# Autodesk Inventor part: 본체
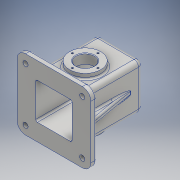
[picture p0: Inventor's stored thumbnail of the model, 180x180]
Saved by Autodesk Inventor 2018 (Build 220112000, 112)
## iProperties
Created: 2022-11
Part Number: 본체
Material: 알루미늄 6061
Document SubType Name: Modeling
Designer: home
Density: 2.7 g/cm^3
Appearance: 알루미늄 - 평지
Mass: 1129.89 g
Surface Area: 1015.9 cm^2
Volume: 418.477 cm^3
Author: home
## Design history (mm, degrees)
sketch "스케치1"
  geometry: L1 (-50, 62)-(50, 62); L2 (65, 47)-(65, -47); L3 (50, -62)-(-50, -62); L4 (-65, -47)-(-65, 47); L5 (-65, 62)-(65, -62); L6 (65, 62)-(-65, -62); A1 r 15 centre (50, 47) between (65, 47) and (50, 62); A2 r 15 centre (50, -47) between (50, -62) and (65, -47); A3 r 15 centre (-50, 47) between (-50, 62) and (-65, 47); A4 r 15 centre (-50, -47) between (-65, -47) and (-50, -62); 1 further point
  constraints: 12 end point, 8 point on circle, 8 point on line, 8 tangent, 4 centre point, 3 equal radius, 2 midpoint, 2 parallel, 1 horizontal, 1 perpendicular
  dimensions: "d2" = 15 radius of A1; "d3" = 46.3532 deg angle of L5 L2; "d4" = 130 distance between parallel lines of L2 L4
extrude "돌출1" new body sketch "스케치1" distance "d5" = 10; taper "d6" = 0 deg
sketch "스케치2"
  geometry: L1 (40, -40)-(-40, -40); L2 (-40, -40)-(-40, 40); L3 (-40, 40)-(40, 40); L4 (40, 40)-(40, -40); L5 (40, -40)-(-40, 40); L6 (-40, -40)-(40, 40); 1 further point
  constraints: 12 end point, 2 midpoint, 2 parallel, 1 horizontal, 1 perpendicular
  dimensions: "d7" = 80 distance of L2.end L3.end; "d8" = 80 distance of L1.end L2.end
extrude "돌출2" join sketch "스케치2" distance "d9" = 107; taper "d10" = 0 deg
node "작업 평면1"
sketch "스케치3"
  geometry: L1 (40, -10)-(40, 45); C1 r 27.5 at (40, 45)
  constraints: 2 end point, 1 centre point, 1 coincident, 1 vertical
  dimensions: "d12" = 55 distance of L1.start L1.end; "d13" = 55 diameter of C1
extrude "돌출3" join sketch "스케치3" stored distance "d14" = 107; taper "d15" = 0 deg
sketch "스케치4"
  geometry: L1 (55, 10)-(38.753, 102.144); L2 (-55, 10)-(-39.372, 98.633); L3 (-55, 10)-(55, 10); 1 further point
  constraints: 6 end point, 1 horizontal
  dimensions: "d22" = 90 distance of L2.start L2.end; "d23" = 110 distance of L1.start L2.start; "d24" = 80 deg angle of L1 L3; "d25" = 20 deg angle of L1 L2; "d26" = 55.90091 distance from line of point (0, 0) L1; "d27" = 10 distance from line of point (0, 0) L3; "d28" = 92.14403 distance from line of L1.end L3
feature "리브1" sketch "스케치4" dims "d29" = 1, "d30" = 10, "d31" = 0, "d32" = 0, "d33" = 1, "d34" = 1
sketch "스케치5"
  geometry: L1 (-32, -32)-(32, -32); L2 (32, -32)-(32, 32); L3 (32, 32)-(-32, 32); L4 (-32, 32)-(-32, -32); L5 (-32, -32)-(32, 32); L6 (32, -32)-(-32, 32); 1 further point
  constraints: 12 end point, 2 midpoint, 2 parallel, 1 horizontal, 1 perpendicular
  dimensions: "d35" = 64 distance of L3.end L2.end; "d36" = 64 distance of L2.end L1.end
extrude "돌출4" cut sketch "스케치5" distance "d37" = 109; taper "d38" = 0 deg
sketch "스케치6"
  geometry: C1 r 20 at (0, 0); 1 further point
  constraints: 1 centre point, 1 coincident
  dimensions: "d39" = 40 diameter of C1
extrude "돌출5" join sketch "스케치6" distance "d40" = 10; taper "d41" = -10 deg
hole "구멍1" diameter "d44" = 32; stored, may be unused: countersink angle "d48" = 90 deg, drill point angle "d50" = 118 deg; dims "d42" = 10, "d43" = 10, "d45" = 6, "d46" = 4, "d47" = 2, "d49" = 8
sketch "스케치7"
  geometry: A1 r 22.5 centre (0, 0) between (0, 22.5) and (22.5, 0); 3 further points
  constraints: 4 point on circle, 1 centre point
  dimensions: "d51" = 45 diameter of A1; "d52" = 59.42432 distance of point (0, -55) A1.end; "d53" = 77.5 distance of point (0, -55) A1.start; "d54" = 32.5 distance of point (0, -55) point (0, -22.5); "d55" = 59.42432 distance of point (0, -55) point (-22.5, 0); "d56" = 55 distance of A1.centre point (0, -55)
hole "구멍2" sketch "스케치7" at (0, 22.5), (22.5, 0), (-22.5, 0), (0, -22.5) diameter "d57" = 3.242; stored, may be unused: countersink angle "d61" = 90 deg, drill point angle "d63" = 118 deg; dims "d58" = 8, "d59" = 4, "d60" = 2, "d62" = 10
hole "구멍3" diameter "d66" = 21; stored, may be unused: countersink angle "d70" = 90 deg, drill point angle "d72" = 118 deg; dims "d64" = 10, "d65" = 10, "d67" = 8, "d68" = 28, "d69" = 4, "d71" = 10
sketch "스케치8"
  geometry: A1 r 15 centre (-50, -47) between (-65, -47) and (-50, -62) reference; A2 r 15 centre (-50, 47) between (-50, 62) and (-65, 47) reference; A3 r 15 centre (50, -47) between (50, -62) and (65, -47) reference; A4 r 15 centre (50, 47) between (65, 47) and (50, 62) reference; 5 further points
  constraints: 4 coincident
hole "구멍4" sketch "스케치8" at (-50, -47), (-50, 47), (50, -47), (50, 47) diameter "d73" = 9; stored, may be unused: countersink angle "d77" = 90 deg, drill point angle "d79" = 118 deg; dims "d74" = 8, "d75" = 28, "d76" = 4, "d78" = 10
fillet "모깎기1" dims "d80" = 8, "d84" = 3
chamfer "모따기1" distance "d81" = 1; stored, may be unused: second distance "d82" = 2, angle "d83" = 45 deg
sketch "스케치9"
  geometry: L1 (72, -96)-(72, 0) reference; L2 (13.763, 18)-(50.237, 18) reference; 2 further points
  constraints: 1 other
  dimensions: "d85" = 40 distance from line of point (32, -7) L1; "d86" = 25 distance from line of point (32, -7) L2
feature "엠보싱1" sketch "스케치9" dims "d7" = 80, "d8" = 80, "d87" = 0.5, "d88" = 0
node "솔리드1"
mirror "미러1"
mirror "미러2"
other parameters: "d11" = 9
